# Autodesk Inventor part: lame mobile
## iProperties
Created: 2002-04
Part Number: lame mobile
Material: Par défaut
Document SubType Name: Modélisation
Designer: thchene
Control State: 0
Master: False
Checked Out: False
Shininess: 20.0
Angle Display Precision: 2
Document Length Units: 11269
Document Angle Units: 11279
Document Time Units: 11290
Document Mass Units: 11283
Document Length Units Precision: 3
Document Angle Units Precision: 2
Compacted: True
Density: 0.0
Volumn: 0.0
Area: 0.0
PropertySet Name: Model Information
Author: thchene
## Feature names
1. Extrusion1
2. Extrusion3
3. Chanfrein1 [Chamfer]
4. Congé1 [Fillet]
